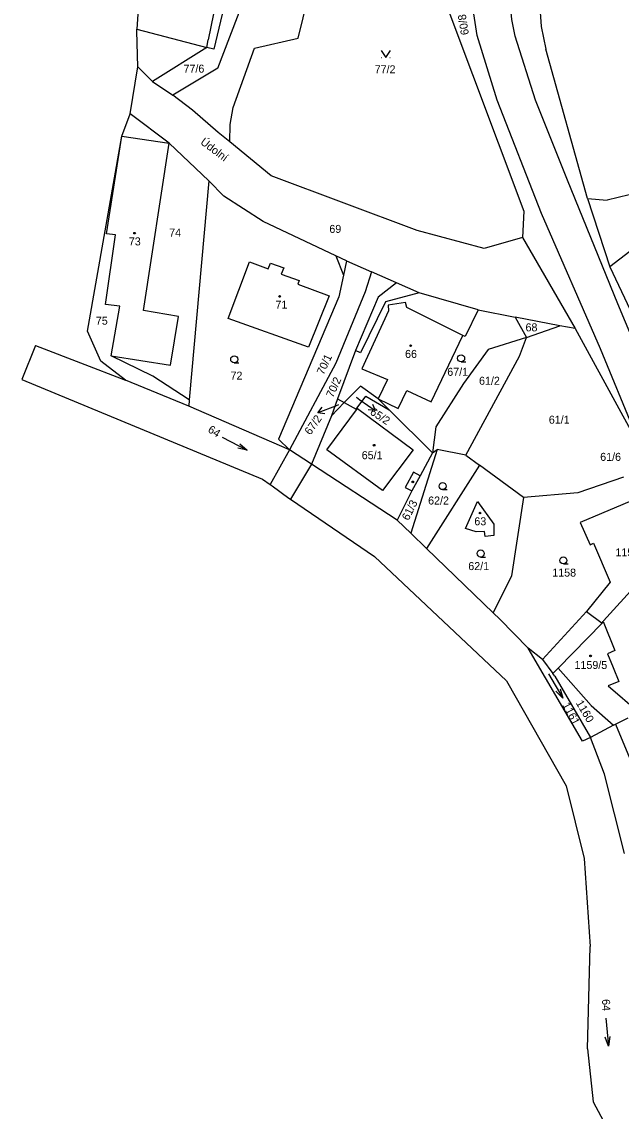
# Model space of a CAD drawing. Extents: x -670359 to -668019, y -978807 to -976674.
# Drawn here: x -670358.7 to -670231.3, y -977942.9 to -977711.4 of the extents above; entities that cross this region are included whole.
import ezdxf

# ---------------------------------------------------------------- set-up
doc = ezdxf.new("R2010")
doc.units = 0
for name, color, linetype in [('Hranice kat_území', 7, 'Continuous'), ('Hranice parcel', 7, 'Continuous'), ('Parcelní čísla', 7, 'Continuous'), ('Pop  PČ popisy', 7, 'Continuous'), ('Vnitřní kresba', 7, 'Continuous'), ('Značky budov', 7, 'Continuous'), ('Značky kultur', 7, 'Continuous')]:
    doc.layers.add(name, color=color, linetype=linetype)

msp = doc.modelspace()

# ---------------------------------------------------------------- linework, layer by layer
at = {"layer": 'Hranice kat_území'}
for points in [[(-670332.34, -977684.03), (-670334.21, -977712.94)], [(-670334.24, -977713.37), (-670334.21, -977712.94)], [(-670334.05, -977720.97), (-670334.24, -977713.37)], [(-670335.64, -977730.96), (-670334.05, -977720.97)], [(-670337.44, -977735.66), (-670335.64, -977730.96)], [(-670344.7, -977777.12), (-670337.44, -977735.66)], [(-670341.86, -977783.46), (-670344.7, -977777.12)], [(-670355.76, -977780.18), (-670358.68, -977787.38)], [(-670355.76, -977780.18), (-670336.61, -977787.5)], [(-670336.61, -977787.5), (-670341.86, -977783.46)], [(-670358.68, -977787.38), (-670307.5, -977808.55)], [(-670307.5, -977808.55), (-670305.92, -977809.69)], [(-670305.92, -977809.69), (-670305.49, -977810)], [(-670305.49, -977810), (-670301.94, -977812.57)], [(-670301.94, -977812.57), (-670301.61, -977812.81)], [(-670301.61, -977812.81), (-670283.75, -977825.01)], [(-670283.75, -977825.01), (-670255.66, -977851.42)], [(-670255.66, -977851.42), (-670242.98, -977873.73)], [(-670242.98, -977873.73), (-670239.16, -977889.17)], [(-670239.16, -977889.17), (-670237.86, -977907.87)], [(-670238.49, -977929.63), (-670237.86, -977907.87)], [(-670238.49, -977929.63), (-670237.25, -977940.88)], [(-670237.25, -977940.88), (-670231.88, -977950.91)]]:
    msp.add_lwpolyline(points, dxfattribs=at)
at = {"layer": 'Hranice parcel'}
for points in [[(-670228.39, -977798.54), (-670235.68, -977780.88), (-670248.21, -977752.09), (-670257.66, -977728.06), (-670261.88, -977714.27), (-670262.87, -977707.81), (-670263.3, -977700.83), (-670262.9, -977694.87), (-670261.36, -977686.41), (-670250.36, -977641.2)], [(-670183.39, -977889.81), (-670193.56, -977862.25), (-670201.26, -977845.22), (-670205.62, -977834.5), (-670231.98, -977771.32), (-670242.71, -977745.05), (-670249.53, -977728.04), (-670253.85, -977714.41), (-670254.54, -977710.9), (-670255.07, -977705.75), (-670255.17, -977699.87), (-670254.7, -977694.67), (-670252.82, -977684.15), (-670242.83, -977643.13)], [(-670306.8, -977670.72), (-670317.87, -977717.22)], [(-670299.92, -977714.89), (-670294.49, -977692.62)], [(-670248.85, -977704.32), (-670248.28, -977712.37)], [(-670317.01, -977721.25), (-670311.54, -977706.97)], [(-670268.34, -977708.07), (-670252.01, -977751.62)], [(-670334.21, -977712.94), (-670319.36, -977716.83)], [(-670248.28, -977712.37), (-670247.28, -977717.18)], [(-670309.21, -977716.99), (-670299.92, -977714.89)], [(-670317.87, -977717.22), (-670319.36, -977716.83)], [(-670313.79, -977729.59), (-670309.21, -977716.99)], [(-670238.46, -977748.91), (-670247.28, -977717.18)], [(-670330.87, -977724.03), (-670334.05, -977720.97)], [(-670317.01, -977721.25), (-670326.57, -977726.94)], [(-670330.87, -977724.03), (-670326.57, -977726.94)], [(-670322.43, -977730.17), (-670326.57, -977726.94)], [(-670314.37, -977733.19), (-670313.79, -977729.59)], [(-670327.36, -977737.17), (-670335.64, -977730.96)], [(-670316.95, -977734.93), (-670322.43, -977730.17)], [(-670314.48, -977736.86), (-670314.37, -977733.19)], [(-670340.71, -977756.44), (-670337.44, -977735.66)], [(-670314.48, -977736.86), (-670316.95, -977734.93)], [(-670332.82, -977772.73), (-670327.36, -977737.17)], [(-670318.94, -977745.15), (-670327.36, -977737.17)], [(-670305.65, -977744.12), (-670314.48, -977736.86)], [(-670318.94, -977745.15), (-670323.11, -977791.67)], [(-670315.76, -977748.45), (-670318.94, -977745.15)], [(-670274.68, -977755.7), (-670305.65, -977744.12)], [(-670227.25, -977747.55), (-670234.3, -977749.26)], [(-670307.4, -977753.79), (-670315.76, -977748.45)], [(-670238.46, -977748.91), (-670233.69, -977763.42)], [(-670238.46, -977748.91), (-670234.3, -977749.26)], [(-670252.01, -977751.62), (-670252.29, -977757.21)], [(-670291.93, -977761.1), (-670307.4, -977753.79)], [(-670220.97, -977753.67), (-670233.69, -977763.42)], [(-670340.89, -977771.47), (-670338.79, -977756.61)], [(-670338.79, -977756.61), (-670340.71, -977756.44)], [(-670260.39, -977759.56), (-670274.68, -977755.7)], [(-670252.29, -977757.21), (-670260.39, -977759.56)], [(-670252.29, -977757.21), (-670241.06, -977776.57)], [(-670289.68, -977762.16), (-670291.93, -977761.1)], [(-670289.68, -977762.16), (-670290.31, -977765.22)], [(-670289.68, -977762.16), (-670284.38, -977764.51)], [(-670314.83, -977774.45), (-670310.26, -977762.41)], [(-670310.26, -977762.41), (-670306.35, -977763.87)], [(-670306.35, -977763.87), (-670305.86, -977762.68)], [(-670305.86, -977762.68), (-670302.99, -977763.66)], [(-670302.99, -977763.66), (-670303.56, -977765.01)], [(-670284.38, -977764.51), (-670285.74, -977768.77)], [(-670279.08, -977766.86), (-670284.38, -977764.51)], [(-670233.69, -977763.42), (-670224.46, -977783.08)], [(-670303.56, -977765.01), (-670299.73, -977766.32)], [(-670299.73, -977766.32), (-670300.05, -977767.12)], [(-670290.31, -977765.22), (-670291.27, -977769.82)], [(-670279.08, -977766.86), (-670282.95, -977769.88)], [(-670274.22, -977768.98), (-670279.08, -977766.86)], [(-670300.05, -977767.12), (-670293.35, -977769.64)], [(-670285.74, -977768.77), (-670291.91, -977783.94)], [(-670261.68, -977772.58), (-670274.22, -977768.98)], [(-670337.86, -977771.81), (-670340.89, -977771.47)], [(-670291.27, -977769.82), (-670304.13, -977800.04)], [(-670293.35, -977769.64), (-670297.75, -977780.49)], [(-670282.95, -977769.88), (-670287.75, -977781.2)], [(-670277.11, -977771.04), (-670280.8, -977771.57)], [(-670280.8, -977771.57), (-670280.73, -977772.77)], [(-670276.88, -977772.08), (-670277.11, -977771.04)], [(-670339.7, -977782.35), (-670337.86, -977771.81)], [(-670325.39, -977773.98), (-670332.82, -977772.73)], [(-670280.73, -977772.77), (-670286.42, -977785.13)], [(-670264.92, -977778), (-670276.88, -977772.08)], [(-670261.68, -977772.58), (-670253.83, -977774.12)], [(-670327.06, -977784.36), (-670325.39, -977773.98)], [(-670297.75, -977780.49), (-670314.83, -977774.45)], [(-670244.34, -977775.98), (-670253.83, -977774.12)], [(-670253.83, -977774.12), (-670251.4, -977778.49)], [(-670251.4, -977778.49), (-670244.34, -977775.98)], [(-670241.06, -977776.57), (-670244.34, -977775.98)], [(-670271.66, -977792.11), (-670264.92, -977778)], [(-670251.4, -977778.49), (-670259.58, -977781)], [(-670252.93, -977782.4), (-670251.4, -977778.49)], [(-670241.06, -977776.57), (-670231.37, -977794.32), (-670228.95, -977798.75), (-670226.38, -977803.45)], [(-670330.84, -977786.66), (-670339.7, -977782.35)], [(-670339.7, -977782.35), (-670327.06, -977784.36)], [(-670287.75, -977781.2), (-670291.56, -977791.5)], [(-670259.58, -977781), (-670264.83, -977788.24)], [(-670264.3, -977803.44), (-670252.93, -977782.4)], [(-670291.91, -977783.94), (-670301.8, -977802.31)], [(-670286.42, -977785.13), (-670280.99, -977787.4)], [(-670323.2, -977793.03), (-670336.61, -977787.5)], [(-670323.11, -977791.67), (-670330.84, -977786.66)], [(-670280.99, -977787.4), (-670282.94, -977791.47)], [(-670286.68, -977788.8), (-670290.14, -977792.3)], [(-670282.94, -977791.47), (-670286.68, -977788.8)], [(-670278.72, -977793.58), (-670276.85, -977789.75)], [(-670276.85, -977789.75), (-670271.66, -977792.11)], [(-670264.83, -977788.24), (-670270.66, -977797.47)], [(-670323.11, -977791.67), (-670323.2, -977793.03)], [(-670291.56, -977791.5), (-670292.89, -977795.08)], [(-670290.14, -977792.3), (-670292.89, -977795.08)], [(-670291.56, -977791.5), (-670290.14, -977792.3)], [(-670290.14, -977792.3), (-670287.6, -977793.72)], [(-670287.6, -977793.72), (-670285.54, -977790.94)], [(-670285.54, -977790.94), (-670280.61, -977793.8)], [(-670282.94, -977791.47), (-670278.72, -977793.58)], [(-670280.61, -977793.8), (-670282.94, -977791.47)], [(-670301.8, -977802.31), (-670323.2, -977793.03)], [(-670271.42, -977802.99), (-670280.61, -977793.8)], [(-670292.89, -977795.08), (-670297.12, -977805.37)], [(-670270.66, -977797.47), (-670271.42, -977802.99)], [(-670304.13, -977800.04), (-670301.8, -977802.31)], [(-670297.12, -977805.37), (-670301.8, -977802.31)], [(-670270.38, -977802.27), (-670276.02, -977820.05)], [(-670271.42, -977802.99), (-670274.02, -977807.85)], [(-670271.42, -977802.99), (-670270.38, -977802.27)], [(-670264.3, -977803.44), (-670270.38, -977802.27)], [(-670264.3, -977803.44), (-670261.39, -977805.59)], [(-670278.88, -977817.26), (-670297.12, -977805.37)], [(-670261.39, -977805.59), (-670272.64, -977823.3)], [(-670252.04, -977812.48), (-670261.39, -977805.59)], [(-670274.02, -977807.85), (-670275.8, -977811.03)], [(-670230.81, -977808.15), (-670240.51, -977811.44)], [(-670275.8, -977811.03), (-670278.88, -977817.26)], [(-670252.04, -977812.48), (-670254.6, -977829.13)], [(-670240.51, -977811.44), (-670252.04, -977812.48)], [(-670226.43, -977812.02), (-670240, -977817.76)], [(-670264.41, -977819.03), (-670261.81, -977813.29)], [(-670261.81, -977813.29), (-670258.33, -977818.11)], [(-670276.02, -977820.05), (-670278.88, -977817.26)], [(-670240, -977817.76), (-670237.87, -977822.5)], [(-670276.02, -977820.05), (-670272.64, -977823.3)], [(-670262.1, -977819.77), (-670264.41, -977819.03)], [(-670260.34, -977819.7), (-670262.1, -977819.77)], [(-670260.18, -977820.74), (-670260.34, -977819.7)], [(-670258.33, -977818.11), (-670258.34, -977820.51)], [(-670258.34, -977820.51), (-670260.18, -977820.74)], [(-670237.87, -977822.5), (-670237.15, -977822.18)], [(-670237.15, -977822.18), (-670233.61, -977830.44)], [(-670272.64, -977823.3), (-670258.49, -977836.94)], [(-670221.47, -977823.73), (-670235.03, -977838.67)], [(-670254.6, -977829.13), (-670258.49, -977836.94)], [(-670233.61, -977830.44), (-670238.69, -977836.65)], [(-670257.11, -977838.28), (-670258.49, -977836.94)], [(-670251.07, -977844.48), (-670257.11, -977838.28)], [(-670238.69, -977836.65), (-670248.05, -977846.9)], [(-670235.03, -977838.67), (-670235.13, -977838.82)], [(-670235.35, -977839.15), (-670244.69, -977848.7)], [(-670235.35, -977839.15), (-670235.13, -977838.82)], [(-670235.13, -977838.82), (-670232.68, -977844.98)], [(-670248.05, -977846.9), (-670251.07, -977844.48)], [(-670239.53, -977864.23), (-670251.07, -977844.48)], [(-670232.68, -977844.98), (-670234.19, -977845.66)], [(-670248.05, -977846.9), (-670245.81, -977849.85)], [(-670234.19, -977845.66), (-670233, -977848.58), (-670231.79, -977851.55)], [(-670244.69, -977848.7), (-670245.81, -977849.85)], [(-670245.4, -977850.39), (-670245.81, -977849.85)], [(-670244.69, -977848.7), (-670237.69, -977856.62)], [(-670245.4, -977850.39), (-670237.84, -977863.45)], [(-670231.79, -977851.55), (-670234.05, -977852.48)], [(-670234.05, -977852.48), (-670227.51, -977858.17)], [(-670237.69, -977856.62), (-670232.94, -977860.84)], [(-670232.52, -977860.64), (-670229.81, -977859.3)], [(-670232.94, -977860.84), (-670237.84, -977863.45)], [(-670232.94, -977860.84), (-670232.52, -977860.64)], [(-670232.52, -977860.64), (-670226.34, -977875.43)], [(-670237.84, -977863.45), (-670239.53, -977864.23)], [(-670234.84, -977871.23), (-670237.84, -977863.45)], [(-670230.6, -977888.08), (-670234.84, -977871.23)]]:
    msp.add_lwpolyline(points, dxfattribs=at)
at = {"layer": 'Parcelní čísla'}
for p, q in [((-670287.52, -977791.17), (-670286.82, -977791.67)), ((-670294.29, -977794.68), (-670295.77, -977794.45)), ((-670291.36, -977792.76), (-670292.03, -977793.02)), ((-670284.18, -977792.62), (-670283.56, -977793.99))]:
    msp.add_line(p, q, dxfattribs=at)
for points in [[(-670286.82, -977791.67), (-670283.56, -977793.99), (-670285.05, -977793.85)], [(-670292.03, -977793.02), (-670295.77, -977794.45), (-670294.82, -977793.28)]]:
    msp.add_lwpolyline(points, dxfattribs=at)
at = {"layer": 'Vnitřní kresba'}
for points in [[(-670316.89, -977704.46), (-670319.04, -977715.24)], [(-670319.36, -977716.83), (-670319.04, -977715.24)], [(-670319.36, -977716.83), (-670330.87, -977724.03)], [(-670337.44, -977735.66), (-670327.36, -977737.17)], [(-670291.93, -977761.1), (-670290.31, -977765.22)], [(-670274.22, -977768.98), (-670281.39, -977770.85)], [(-670281.39, -977770.85), (-670286.71, -977781.69)], [(-670261.68, -977772.58), (-670264.44, -977778.24)], [(-670264.44, -977778.24), (-670264.92, -977778)], [(-670286.71, -977781.69), (-670287.75, -977781.2)], [(-670293.82, -977802.35), (-670287.36, -977793.52)], [(-670287.36, -977793.52), (-670275.5, -977802.32)], [(-670301.8, -977802.31), (-670305.92, -977809.69)], [(-670282.04, -977810.99), (-670293.82, -977802.35)], [(-670275.5, -977802.32), (-670282.04, -977810.99)], [(-670297.12, -977805.37), (-670301.61, -977812.81)], [(-670275.45, -977807.04), (-670277.23, -977810.3)], [(-670274.02, -977807.85), (-670275.45, -977807.04)], [(-670277.23, -977810.3), (-670275.8, -977811.03)], [(-670238.69, -977836.65), (-670235.35, -977839.15)]]:
    msp.add_lwpolyline(points, dxfattribs=at)
at = {"layer": 'Značky budov'}
for centre in [(-670334.72, -977756.29), (-670303.88, -977769.73), (-670276.05, -977780.2), (-670283.8, -977801.35), (-670261.3, -977815.76), (-670237.81, -977846.11)]:
    msp.add_circle(centre, 0.175, dxfattribs=at)
at = {"layer": 'Značky kultur'}
for p, q in [((-670282.27, -977718.96), (-670282.17, -977718.96)), ((-670280.47, -977718.96), (-670280.37, -977718.96)), ((-670313.53, -977783.85), (-670312.53, -977783.85)), ((-670265.32, -977783.63), (-670264.32, -977783.63)), ((-670316.09, -977799.66), (-670310.77, -977802.42)), ((-670269.25, -977810.79), (-670268.25, -977810.79)), ((-670261.17, -977825.1), (-670260.17, -977825.1)), ((-670243.59, -977826.57), (-670242.59, -977826.57)), ((-670246.74, -977849.89), (-670243.72, -977855.07)), ((-670234.55, -977923.07), (-670234.01, -977929.05))]:
    msp.add_line(p, q, dxfattribs=at)
for points in [[(-670282.32, -977717.46), (-670281.32, -977718.96), (-670280.32, -977717.46)], [(-670312.31, -977801.06), (-670310.77, -977802.42), (-670312.77, -977801.94)], [(-670244.29, -977853.09), (-670243.72, -977855.07), (-670245.16, -977853.6)], [(-670233.69, -977927.01), (-670234.01, -977929.05), (-670234.69, -977927.1)]]:
    msp.add_lwpolyline(points, dxfattribs=at)
for centre, radius in [((-670334.72, -977756.29), 0.175), ((-670303.88, -977769.73), 0.175), ((-670276.05, -977780.2), 0.175), ((-670313.53, -977783.1), 0.75), ((-670265.32, -977782.88), 0.75), ((-670283.8, -977801.35), 0.175), ((-670275.58, -977809.14), 0.175), ((-670269.25, -977810.04), 0.75), ((-670261.3, -977815.76), 0.175), ((-670261.17, -977824.35), 0.75), ((-670243.59, -977825.82), 0.75), ((-670237.81, -977846.11), 0.175)]:
    msp.add_circle(centre, radius, dxfattribs=at)

# ---------------------------------------------------------------- texts
at = {"layer": 'Parcelní čísla'}
for s, rotation, p in [('60/8', 99.1577, (-670263.65, -977714.04)), ('70/1', 65.1858, (-670294.55, -977786.52)), ('70/2', 65.4401, (-670292.55, -977791.37)), ('65/2', 326.616, (-670284.83, -977794.67)), ('67/2', 55.1271, (-670297.35, -977799.31)), ('64', 327.6671, (-670319.29, -977798.43)), ('61/3', 63.3011, (-670276.5, -977817.48)), ('1161', 298.0273, (-670243.87, -977856.53)), ('1160', 300.4385, (-670241, -977856.11)), ('64', 272.852, (-670235.39, -977919.08))]:
    msp.add_text(s, height=1.7, rotation=rotation, dxfattribs=at).set_placement(p)
for s, height, p in [('77/6', 1.7, (-670324.31, -977722.18)), ('77/2', 1.7, (-670283.69, -977722.32)), ('74', 1.7, (-670327.35, -977757)), ('69', 1.7, (-670293.32, -977756.24)), ('73', 1.7, (-670335.93, -977758.89)), ('71', 1.7, (-670304.77, -977772.33)), ('75', 1.7, (-670342.94, -977775.74)), ('68', 1.7, (-670251.63, -977777.16)), ('66', 1.7, (-670277.23, -977782.8)), ('67/1', 1.7, (-670268.26, -977786.6)), ('72', 1.7, (-670314.32, -977787.41)), ('61/2', 1.7, (-670261.51, -977788.5)), ('65/2', 0.1, (-670287.68, -977791.17)), ('67/2', 0.1, (-670291.52, -977792.76)), ('61/1', 1.7, (-670246.68, -977796.77)), ('65/1', 1.7, (-670286.44, -977804.32)), ('61/6', 1.7, (-670235.76, -977804.67)), ('62/2', 1.7, (-670272.33, -977813.95)), ('63', 1.7, (-670262.51, -977818.36)), ('1157', 1.7, (-670232.52, -977824.95)), ('62/1', 1.7, (-670263.79, -977827.88)), ('1158', 1.7, (-670245.95, -977829.27)), ('1159/5', 1.7, (-670241.22, -977848.89))]:
    msp.add_text(s, height=height, dxfattribs=at).set_placement(p)
at = {"layer": 'Pop  PČ popisy'}
msp.add_text('Údolní', height=1.7, rotation=322.8528, dxfattribs=at).set_placement((-670320.87, -977737.22))

doc.saveas('drawing.dxf')
